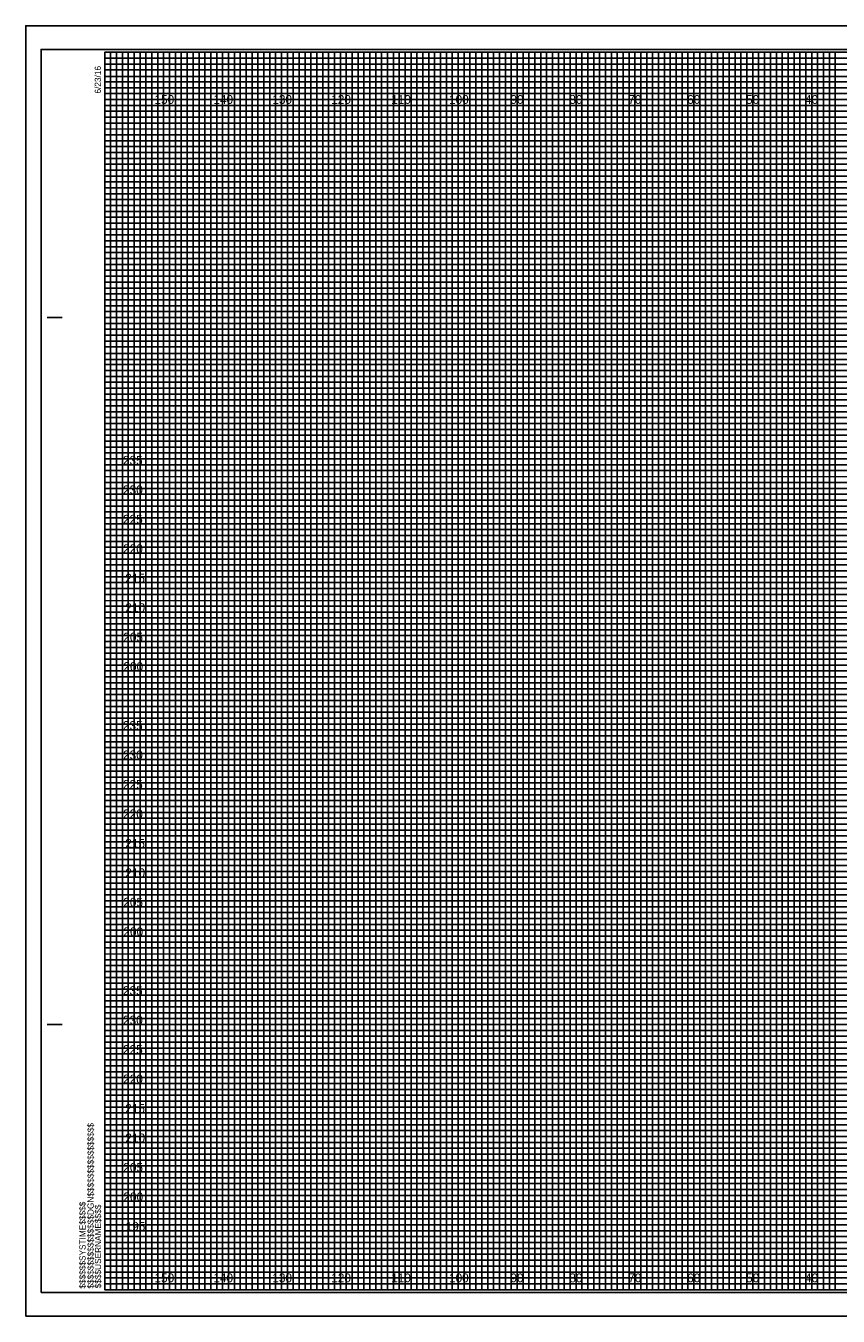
# Model space of a CAD drawing. Extents: x -13 to 323, y -5 to 434.
# Drawn here: x -13.4 to 124.5, y 215.5 to 434.5 of the extents above; entities that cross this region are included whole.
import ezdxf

# ---------------------------------------------------------------- set-up
doc = ezdxf.new("R2010")
doc.units = 0
for name, color, linetype in [('Prop XS Elevation Labels', 7, 'Continuous'), ('Prop XS Offset Labels', 7, 'Continuous'), ('Sheet Cross Section CELL', 7, 'Continuous'), ('Sheet Cross Section Grid Major CELL', 7, 'Continuous'), ('Sheet Cross Section Grid Middle CELL', 7, 'Continuous'), ('Sheet Cross Section Grid Minor 1 CELL', 7, 'Continuous'), ('Sheet Cross Section Grid Minor 2 CELL', 7, 'Continuous'), ('Sheet Cutting Line CELL', 7, 'Continuous'), ('Sheet DOT Grid CELL', 7, 'Continuous'), ('Sheet Plot Border Inside CELL', 7, 'Continuous'), ('Sheet Plot Border Outside CELL', 7, 'Continuous')]:
    doc.layers.add(name, color=color, linetype=linetype)

msp = doc.modelspace()

# ---------------------------------------------------------------- linework, layer by layer
at = {"layer": 'Sheet Cross Section CELL'}
for p, q in [((-9.8, 385), (-7.3, 385)), ((-9.7, 385), (-7.2, 385)), ((-9.8, 265), (-7.3, 265)), ((-9.7, 265), (-7.2, 265)), ((0, 220), (0, 220)), ((0, 220), (0, 220)), ((0, 220), (0, 220)), ((0, 220), (0, 220)), ((0, 220), (0, 220)), ((0, 220), (0, 220)), ((0, 220), (0, 220))]:
    msp.add_line(p, q, dxfattribs=at)
msp.add_lwpolyline([(320, 430), (0, 430), (0, 220), (320, 220)], close=True, dxfattribs=at)
at = {"layer": 'Sheet Cross Section Grid Major CELL'}
for p, q in [((10, 430), (0, 430)), ((10, 220), (10, 430)), ((30, 430), (20, 430)), ((20, 430), (20, 220)), ((30, 220), (30, 430)), ((50, 430), (40, 430)), ((40, 430), (40, 220)), ((50, 220), (50, 430)), ((70, 430), (60, 430)), ((60, 430), (60, 220)), ((70, 220), (70, 430)), ((90, 430), (80, 430)), ((80, 430), (80, 220)), ((90, 220), (90, 430)), ((110, 430), (100, 430)), ((100, 430), (100, 220)), ((110, 220), (110, 430)), ((130, 430), (120, 430)), ((120, 430), (120, 220)), ((20, 220), (10, 220)), ((40, 220), (30, 220)), ((60, 220), (50, 220)), ((80, 220), (70, 220)), ((100, 220), (90, 220)), ((120, 220), (110, 220))]:
    msp.add_line(p, q, dxfattribs=at)
for points in [[(0, 420), (320, 420), (320, 410), (0, 410)], [(0, 400), (320, 400), (320, 390), (0, 390)], [(0, 380), (320, 380), (320, 370), (0, 370)], [(0, 360), (320, 360), (320, 350), (0, 350)], [(0, 340), (320, 340), (320, 330), (0, 330)], [(0, 320), (320, 320), (320, 310), (0, 310)], [(0, 300), (320, 300), (320, 290), (0, 290)], [(0, 280), (320, 280), (320, 270), (0, 270)], [(0, 260), (320, 260), (320, 250), (0, 250)], [(0, 240), (320, 240), (320, 230), (0, 230)]]:
    msp.add_lwpolyline(points, dxfattribs=at)
at = {"layer": 'Sheet Cross Section Grid Middle CELL'}
for points in [[(0, 430), (5, 430), (5, 220), (15, 220), (15, 430), (25, 430), (25, 220), (35, 220), (35, 430), (45, 430), (45, 220), (55, 220), (55, 430), (65, 430), (65, 220), (75, 220), (75, 430), (85, 430), (85, 220), (95, 220), (95, 430), (105, 430), (105, 220), (115, 220), (115, 430), (125, 430)], [(0, 425), (275, 425)], [(0, 405), (320, 405), (320, 415), (0, 415)], [(0, 385), (320, 385), (320, 395), (0, 395)], [(0, 365), (320, 365), (320, 375), (0, 375)], [(0, 345), (320, 345), (320, 355), (0, 355)], [(0, 325), (320, 325), (320, 335), (0, 335)], [(0, 305), (320, 305), (320, 315), (0, 315)], [(0, 285), (320, 285), (320, 295), (0, 295)], [(0, 265), (320, 265), (320, 275), (0, 275)], [(0, 245), (320, 245), (320, 255), (0, 255)], [(0, 225), (320, 225), (320, 235), (0, 235)]]:
    msp.add_lwpolyline(points, dxfattribs=at)
at = {"layer": 'Sheet Cross Section Grid Minor 1 CELL'}
for p, q in [((0, 429), (260, 429)), ((260, 427.98), (0, 427.98)), ((0, 427.98), (0, 427)), ((0, 427), (260, 427)), ((260, 425.89), (0, 425.89)), ((0, 425.89), (0, 424)), ((0, 424), (320, 424))]:
    msp.add_line(p, q, dxfattribs=at)
for points in [[(0, 423), (270, 423), (320, 423), (320, 422), (0, 422)], [(0, 421), (320, 421), (320, 419), (0, 419)], [(0, 418), (320, 418), (320, 417), (0, 416.98)], [(0, 416), (320, 416), (320, 414), (0, 414)], [(0, 413), (320, 413), (320, 412), (0, 412)], [(0, 411), (320, 411), (320, 409), (0, 409)], [(0, 408), (320, 408), (320, 407), (0, 407)], [(0, 406), (320, 406), (320, 404), (0, 404)], [(0, 403), (320, 403), (320, 402), (0, 402)], [(0, 401), (320, 401), (320, 399), (0, 399)], [(0, 398), (320, 398), (320, 397), (0, 397)], [(0, 396), (320, 396), (320, 393.95), (320, 393), (320, 392), (0, 392)], [(0, 394), (320, 394), (320, 393), (0, 393)], [(0, 391), (320, 391), (320, 389), (0, 389.03)], [(0, 389.03), (320, 389), (320, 388), (0, 388)], [(0, 387), (320, 387), (320, 386), (0, 386)], [(0, 384), (320, 384), (320, 383), (0, 383)], [(0, 382), (320, 382), (320, 381), (0, 381)], [(-0.07, 378.89), (320, 378.89), (320, 377.88), (-0.07, 377.88)], [(0, 377), (320, 377), (320, 376), (0, 376)], [(0, 374), (320, 374), (320, 373), (0, 373)], [(0, 372), (320, 372), (320, 371), (0, 371)], [(0, 369), (320, 369), (320, 368), (0, 368)], [(0, 367), (320, 367), (320, 366), (0, 366)], [(0, 364), (320, 364), (320, 363), (0, 363)], [(0, 362), (320, 362), (320, 361), (0, 361)], [(0, 359), (320, 359), (319.99, 357.98), (0, 358)], [(0, 357), (320, 357), (320, 356), (0, 356)], [(0, 354), (320, 354), (320, 353), (0, 353)], [(0, 352), (320, 352), (320, 351), (0, 351)], [(0, 349), (320, 349), (320, 348), (0, 348)], [(0, 347), (320, 347), (320, 346), (0, 346)], [(0, 344), (320, 344), (320, 343), (0, 343)], [(0, 342), (320, 342), (320, 341), (0, 341)], [(0, 339), (320, 339), (320, 338), (0, 338)], [(0, 336.99), (320.07, 336.91), (320, 336), (0, 336)], [(0, 334), (320, 334), (320, 333), (0, 333)], [(0, 332), (320, 332), (320, 331), (0, 331)], [(0, 329), (320, 329), (320, 328), (0, 328)], [(0, 327), (320, 327), (320, 326), (0, 326)], [(0, 324), (320, 324), (320, 323), (0, 323)], [(0, 322), (320, 322), (320, 321), (0, 321)], [(0, 319), (320, 319), (320, 318), (0, 318)], [(0, 317), (320, 317), (320, 316), (0, 316)], [(0, 314), (320, 314), (320, 313), (0, 313)], [(0, 312), (320, 312), (320, 311), (0, 311)], [(0, 309), (320, 309), (320, 308), (0, 308)], [(0, 307), (320, 307), (320, 306), (0, 306)], [(0, 304), (320, 304), (320, 303), (0, 303)], [(0, 302), (320, 302), (320, 301), (0, 301)], [(0, 299), (320, 299), (319.99, 297.98), (0, 298)], [(0, 297), (320, 297), (320, 296), (0, 296)], [(0, 294), (320, 294), (320, 293), (0, 293)], [(0, 292), (320, 292), (320, 291), (0, 291)], [(0, 289), (320, 289), (320, 288), (0, 288)], [(0, 287), (320, 287), (320, 286), (0, 286)], [(0, 284), (320, 284), (320, 283), (0, 283)], [(0, 282), (320, 282), (320, 281), (0, 281)], [(0, 279), (320, 279), (320, 278), (0, 278)], [(0, 276.99), (320.07, 276.91), (320, 276), (0, 276)], [(0, 274), (320, 274), (320, 273), (0, 273)], [(0, 272), (320, 272), (320, 271), (0, 271)], [(0, 269), (320, 269), (320, 268), (0, 268)], [(0, 267), (320, 267), (320, 266), (0, 266)], [(0, 264), (320, 264), (320, 263), (0, 263)], [(0, 262), (320, 262), (320, 261), (0, 261)], [(0, 259), (320, 259), (320, 258), (0, 258)], [(0, 257), (320, 257), (320, 256), (0, 256)], [(0, 254), (320, 254), (320, 253), (0, 253)], [(0, 252), (320, 252), (320, 251), (0, 251)], [(0, 249), (320, 249), (320, 248), (0, 248)], [(0, 247), (320, 247), (320, 246), (0, 246)], [(0, 244), (320, 244), (320, 243), (0, 243)], [(0, 242), (320, 242), (320, 241), (0, 241)], [(0, 239), (320, 239), (320, 238), (0, 238)], [(0, 237), (320, 237), (320, 236), (0, 236)], [(0, 234), (320, 234), (320, 233), (0, 233)], [(0, 232), (320, 232), (320, 231), (0, 231)], [(0, 229), (320, 229), (320, 228), (0, 228)], [(0, 227), (320, 227), (320, 226), (0, 226)], [(0, 224), (320, 224), (320, 223), (0, 223)], [(0, 222), (320, 222), (320, 221), (0, 221)]]:
    msp.add_lwpolyline(points, dxfattribs=at)
at = {"layer": 'Sheet Cross Section Grid Minor 2 CELL'}
for points in [[(0, 220), (1, 220), (1, 430), (2, 430), (2, 220)], [(2, 220), (3, 220), (3, 430), (4, 430), (4, 220)], [(5, 220), (6, 220), (6, 430), (7, 430), (7, 220)], [(7, 220), (8, 220), (8, 430), (9, 430), (9, 220)], [(10, 220), (11, 220), (11, 430), (12, 430), (12, 220)], [(12, 220), (13, 220), (13, 430), (14, 430), (14, 220)], [(15, 220), (16, 220), (16, 430), (17, 430), (17, 220)], [(17, 220), (18, 220), (18, 430), (19, 430), (19, 220)], [(20, 220), (21, 220), (21, 430), (22, 430), (22, 220)], [(22, 220), (23, 220), (23, 430), (24, 430), (24, 220)], [(25, 220), (26, 220), (26, 430), (27, 430), (27, 220)], [(27, 220), (28, 220), (28, 430), (29, 430), (29, 220)], [(30, 220), (31, 220), (31, 430), (32, 430), (32, 220)], [(32, 220), (33, 220), (33, 430), (34, 430), (34, 220)], [(35, 220), (36, 220), (36, 430), (37, 430), (37, 220)], [(37, 220), (38, 220), (38, 430), (39, 430), (39, 220)], [(40, 220), (41, 220), (41, 430), (42, 430), (42, 220)], [(42, 220), (43, 220), (43, 430), (44, 430), (44, 220)], [(45, 220), (46, 220), (46, 430), (47, 430), (47, 220)], [(47, 220), (48, 220), (48, 430), (49, 430), (49, 220)], [(50, 220), (51, 220), (51, 430), (52, 430), (52, 220)], [(52, 220), (53, 220), (53, 430), (54, 430), (54, 220)], [(55, 220), (56, 220), (56, 430), (57, 430), (57, 220)], [(57, 220), (58, 220), (58, 430), (59, 430), (59, 220)], [(60, 220), (61, 220), (61, 430), (62, 430), (62, 220)], [(62, 220), (63, 220), (63, 430), (64, 430), (64, 220)], [(65, 220), (66, 220), (66, 430), (67, 430), (67, 220)], [(67, 220), (68, 220), (68, 430), (69, 430), (69, 220)], [(70, 220), (71, 220), (71, 430), (72, 430), (72, 220)], [(72, 220), (73, 220), (73, 430), (74, 430), (74, 220)], [(75, 220), (76, 220), (76, 430), (77, 430), (77, 220)], [(77, 220), (78, 220), (78, 430), (79, 430), (79, 220)], [(80, 220), (81, 220), (81, 430), (82, 430), (82, 220)], [(82, 220), (83, 220), (83, 430), (84, 430), (84, 220)], [(85, 220), (86, 220), (86, 430), (87, 430), (87, 220)], [(87, 220), (88, 220), (88, 430), (89, 430), (89, 220)], [(90, 220), (91, 220), (91, 430), (92, 430), (92, 220)], [(92, 220), (93, 220), (93, 430), (94, 430), (94, 220)], [(95, 220), (96, 220), (96, 430), (97, 430), (97, 220)], [(97, 220), (98, 220), (98, 430), (99, 430), (99, 220)], [(100, 220), (101, 220), (101, 430), (102, 430), (102, 220)], [(102, 220), (103, 220), (103, 430), (104, 430), (104, 220)], [(105, 220), (106, 220), (106, 430), (107, 430), (107, 220)], [(107, 220), (108, 220), (108, 430), (109, 430), (109, 220)], [(110, 220), (111, 220), (111, 430), (112, 430), (112, 220)], [(112, 220), (113, 220), (113, 430), (114, 430), (114, 220)], [(115, 220), (116, 220), (116, 430), (117, 430), (117, 220)], [(117, 220), (118, 220), (118, 430), (119, 430), (119, 220)], [(120, 220), (121, 220), (121, 430), (122, 430), (122, 220)], [(122, 220), (123, 220), (123, 430), (124, 430), (124, 220)]]:
    msp.add_lwpolyline(points, dxfattribs=at)
at = {"layer": 'Sheet Cutting Line CELL'}
for p, q in [((323.3, 434.5), (-13.4, 434.5)), ((-13.4, 434.5), (-13.4, 215.5)), ((-13.4, 215.5), (323.3, 215.5))]:
    msp.add_line(p, q, dxfattribs=at)
at = {"layer": 'Sheet DOT Grid CELL'}
for p, q in [((10, 220), (10, 430)), ((20, 220), (20, 430)), ((30, 220), (30, 430)), ((40, 220), (40, 430)), ((50, 220), (50, 430)), ((60, 220), (60, 430)), ((70, 220), (70, 430)), ((80, 220), (80, 430)), ((90, 220), (90, 430)), ((100, 220), (100, 430)), ((110, 220), (110, 430)), ((120, 220), (120, 430)), ((0, 420), (320, 420)), ((0, 410), (320, 410)), ((0, 400), (320, 400)), ((0, 390), (320, 390)), ((0, 380), (320, 380)), ((0, 370), (320, 370)), ((0, 360), (320, 360)), ((0, 350), (320, 350)), ((0, 340), (320, 340)), ((0, 330), (320, 330)), ((0, 320), (320, 320)), ((0, 310), (320, 310)), ((0, 300), (320, 300)), ((0, 290), (320, 290)), ((0, 280), (320, 280)), ((0, 270), (320, 270)), ((0, 260), (320, 260)), ((0, 250), (320, 250)), ((0, 240), (320, 240)), ((0, 230), (320, 230))]:
    msp.add_line(p, q, dxfattribs=at)
at = {"layer": 'Sheet Plot Border Inside CELL'}
msp.add_lwpolyline([(-10.8, 219.5), (322.4, 219.5), (322.4, 430.5), (-10.8, 430.5)], close=True, dxfattribs=at)
at = {"layer": 'Sheet Plot Border Outside CELL'}
msp.add_lwpolyline([(-13.4, 215.5), (323.3, 215.5), (323.3, 434.5), (-13.4, 434.5)], close=True, dxfattribs=at)

# ---------------------------------------------------------------- texts
at = {"layer": 'Prop XS Elevation Labels'}
for s, p in [('235', (3.09, 360)), ('230', (3.11, 355)), ('225', (3.1, 350)), ('220', (3.12, 345)), ('215', (3.48, 340)), ('210', (3.5, 335)), ('205', (3.15, 330)), ('200', (3.17, 325)), ('235', (3.09, 315)), ('230', (3.11, 310)), ('225', (3.1, 305)), ('220', (3.12, 300)), ('215', (3.48, 295)), ('210', (3.5, 290)), ('205', (3.15, 285)), ('200', (3.17, 280)), ('235', (3.09, 270)), ('230', (3.11, 265)), ('225', (3.1, 260)), ('220', (3.12, 255)), ('215', (3.48, 250)), ('210', (3.5, 245)), ('205', (3.15, 240)), ('200', (3.17, 235)), ('195', (3.55, 230))]:
    msp.add_text(s, height=1.5, dxfattribs=at).set_placement(p)
at = {"layer": 'Prop XS Offset Labels'}
for s, p in [('150', (8.44, 421.25)), ('140', (18.44, 421.25)), ('130', (28.44, 421.25)), ('120', (38.44, 421.25)), ('110', (48.62, 421.25)), ('100', (58.44, 421.25)), ('90', (68.86, 421.25)), ('80', (78.86, 421.25)), ('70', (88.86, 421.25)), ('60', (98.86, 421.25)), ('50', (108.86, 421.25)), ('40', (118.86, 421.25)), ('150', (8.44, 221.25)), ('140', (18.44, 221.25)), ('130', (28.44, 221.25)), ('120', (38.44, 221.25)), ('110', (48.62, 221.25)), ('100', (58.44, 221.25)), ('90', (68.86, 221.25)), ('80', (78.86, 221.25)), ('70', (88.86, 221.25)), ('60', (98.86, 221.25)), ('50', (108.86, 221.25)), ('40', (118.86, 221.25))]:
    msp.add_text(s, height=1.5, dxfattribs=at).set_placement(p)
at = {"layer": 'Sheet Cross Section CELL'}
for s, p in [('6/23/16', (-0.65, 423)), ('$$$$$$$$$$$$$$$$DGN$$$$$$$$$$$$$$$$', (-1.88, 220.18)), ('$$$$$$SYSTIME$$$$$', (-3.26, 220.18)), ('$$$$USERNAME$$$$', (-0.62, 220.23))]:
    msp.add_text(s, height=1.05, rotation=90, dxfattribs=at).set_placement(p)

doc.saveas('drawing.dxf')
